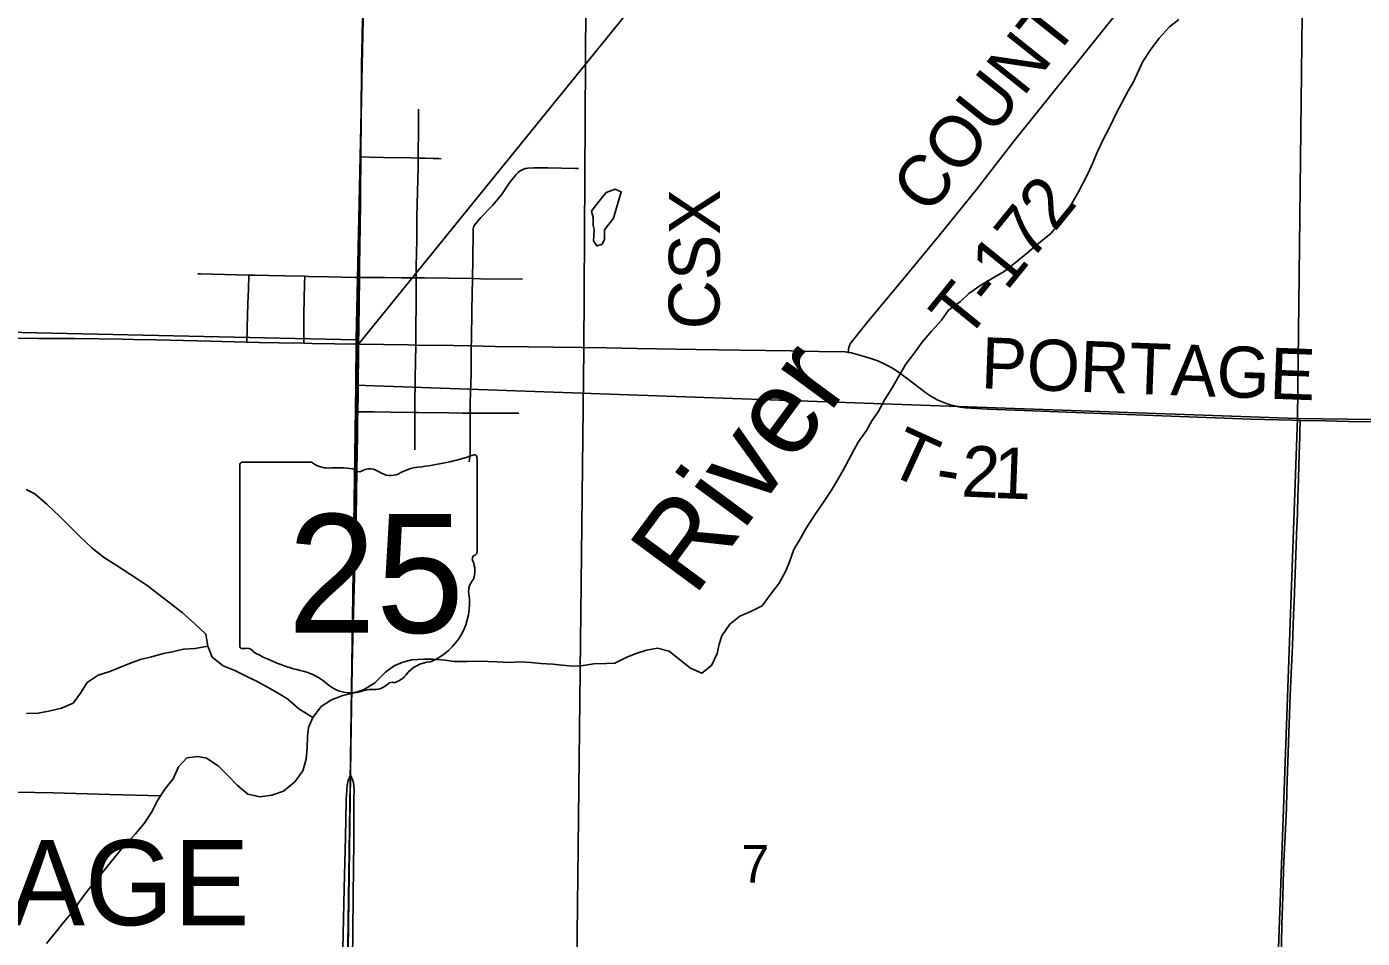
# Model space of a CAD drawing. Extents: x -107 to 120, y -81 to 213.
# Drawn here: x -76.39 to -68.55, y -30.12 to -24.78 of the extents above; entities that cross this region are included whole.
import ezdxf

# ---------------------------------------------------------------- set-up
doc = ezdxf.new("R2010")
doc.units = 0
for name, color, linetype in [('Default', 7, 'Continuous'), ('GM_X_City_Street', 7, 'Continuous'), ('GM_X_Corporation_Text', 7, 'Continuous'), ('GM_X_Major_River', 7, 'Continuous'), ('GM_X_Minor_Lake', 7, 'Continuous'), ('GM_X_Minor_River', 7, 'Continuous'), ('GM_X_Minor_River_Text', 7, 'Continuous'), ('GM_X_Rail_Line', 7, 'Continuous'), ('GM_X_Rail_Line_Text', 7, 'Continuous'), ('GM_X_Section', 7, 'Continuous'), ('GM_X_Section_Text', 7, 'Continuous'), ('GM_X_State_Location', 7, 'Continuous'), ('GM_X_State_Route', 7, 'Continuous'), ('GM_X_State_Shield', 7, 'Continuous'), ('GM_X_Township', 7, 'Continuous'), ('GM_X_Township_Road', 7, 'Continuous'), ('GM_X_Township_Road_Text', 7, 'Continuous')]:
    doc.layers.add(name, color=color, linetype=linetype)

msp = doc.modelspace()

# ---------------------------------------------------------------- linework, layer by layer
at = {"layer": 'Default'}
msp.add_line((-74.4427, -26.637), (119.9981, 213.2739), dxfattribs=at)
at = {"layer": 'GM_X_City_Street'}
for points in [[(-74.1072, -26.6428), (-74.1072, -26.6296), (-74.1074, -26.5878), (-74.1066, -26.5245), (-74.1061, -26.4914), (-74.1056, -26.4507), (-74.1052, -26.4185), (-74.1051, -26.3742), (-74.1051, -26.3129), (-74.1049, -26.2909), (-74.1045, -26.2483), (-74.1042, -26.2136), (-74.1039, -26.1701), (-74.1034, -26.1146), (-74.1009, -26.0166), (-74.1007, -25.9843), (-74.1006, -25.9353), (-74.1003, -25.9203), (-74.0999, -25.8891), (-74.0936, -25.5993), (-74.0936, -25.5505), (-74.0935, -25.5459), (-74.093, -25.518), (-74.0932, -25.502), (-74.0919, -25.4041), (-74.0914, -25.3665), (-74.0907, -25.3064), (-74.09, -25.2594)], [(-74.4297, -25.5388), (-74.3782, -25.5402), (-74.2972, -25.5425), (-74.1348, -25.5444), (-74.0935, -25.5459), (-74.0538, -25.5473), (-74.0054, -25.5482), (-73.9733, -25.5494), (-73.9575, -25.5503)], [(-73.7813, -26.6482), (-73.7808, -26.6156), (-73.778, -26.4355), (-73.7745, -26.2534), (-73.7724, -26.1409), (-73.7708, -25.9772), (-73.7697, -25.9609), (-73.7654, -25.9452), (-73.7567, -25.9315), (-73.7459, -25.9191), (-73.7244, -25.8951), (-73.6558, -25.8248), (-73.6349, -25.7997), (-73.6047, -25.761), (-73.5582, -25.6936), (-73.5286, -25.6544), (-73.5181, -25.6419), (-73.5066, -25.6302), (-73.4936, -25.6203), (-73.4792, -25.6127), (-73.4637, -25.6077), (-73.4476, -25.6049), (-73.4149, -25.603), (-73.333, -25.6029), (-73.1693, -25.6071), (-73.153, -25.6073)], [(-75.386, -26.2245), (-75.37, -26.2245), (-75.0867, -26.2331), (-75.0515, -26.2336), (-74.9716, -26.2349), (-74.8754, -26.2364), (-74.7582, -26.2396), (-74.737, -26.2399), (-74.6164, -26.2425), (-74.4626, -26.2458), (-74.4378, -26.2464)], [(-75.0981, -26.6259), (-75.0974, -26.602), (-75.0965, -26.5701), (-75.0956, -26.5371), (-75.0938, -26.4728), (-75.0917, -26.3981), (-75.0893, -26.3147), (-75.0867, -26.2331)], [(-74.7646, -26.6325), (-74.7643, -26.5961), (-74.7633, -26.4641), (-74.7592, -26.2827), (-74.7582, -26.2396)], [(-74.4378, -26.2464), (-74.2889, -26.247), (-74.188, -26.248), (-74.1045, -26.2483), (-74.0561, -26.2484), (-73.7745, -26.2534), (-73.7264, -26.2543), (-73.4813, -26.2565)], [(-74.1119, -27.2584), (-74.1124, -27.2262), (-74.1128, -27.194), (-74.1126, -27.1778), (-74.1127, -27.0799), (-74.1132, -27.0506), (-74.1134, -27.0383), (-74.1132, -26.9998), (-74.112, -26.9511), (-74.1111, -26.8862), (-74.111, -26.8537), (-74.1101, -26.8375), (-74.1082, -26.7398), (-74.1072, -26.6428)], [(-73.7937, -27.3273), (-73.7901, -27.3013), (-73.7887, -27.2789), (-73.7879, -27.261), (-73.7874, -27.224), (-73.7879, -27.1423), (-73.7877, -27.0771), (-73.7882, -27.0418), (-73.7879, -27.0252), (-73.7869, -26.9797), (-73.7836, -26.865), (-73.7829, -26.8156), (-73.7813, -26.6482)], [(-74.4474, -27.0348), (-74.4069, -27.0345), (-74.3528, -27.0341), (-74.2547, -27.0359), (-74.1134, -27.0383), (-74.0932, -27.0386), (-73.9111, -27.0415), (-73.8305, -27.0417), (-73.7882, -27.0418), (-73.7391, -27.0419), (-73.6821, -27.042), (-73.5839, -27.0428), (-73.5513, -27.043), (-73.5029, -27.0427)]]:
    msp.add_lwpolyline(points, dxfattribs=at)
at = {"layer": 'GM_X_Major_River'}
for points in [[(-69.6305, -24.7339), (-69.6847, -24.7759), (-69.745, -24.8419), (-69.7953, -24.9119), (-69.8416, -24.98), (-69.8739, -25.0521), (-69.8981, -25.1022), (-69.9262, -25.1522), (-69.9625, -25.2183), (-69.9968, -25.2844), (-70.0331, -25.3585), (-70.0714, -25.4326), (-70.1056, -25.5027), (-70.1339, -25.5748), (-70.1641, -25.6389), (-70.1904, -25.691), (-70.2186, -25.7431), (-70.2488, -25.7991), (-70.2891, -25.8632), (-70.3213, -25.9173), (-70.3796, -25.9873), (-70.4539, -26.0472), (-70.5162, -26.0992), (-70.5905, -26.1612), (-70.6547, -26.2111), (-70.719, -26.249), (-70.7912, -26.2909), (-70.8615, -26.3409), (-70.9117, -26.3869), (-70.982, -26.4388), (-71.0223, -26.4969), (-71.0805, -26.5609), (-71.1348, -26.6269), (-71.1871, -26.6969), (-71.2314, -26.755), (-71.2717, -26.825), (-71.312, -26.8931), (-71.3543, -26.9632), (-71.3946, -27.0353), (-71.4308, -27.0873), (-71.463, -27.1434), (-71.5113, -27.2134), (-71.5496, -27.2855), (-71.5879, -27.3556), (-71.6241, -27.4217), (-71.6684, -27.4937), (-71.7188, -27.5698), (-71.7691, -27.6458), (-71.8154, -27.7179), (-71.8476, -27.774), (-71.8879, -27.842), (-71.9162, -27.9202), (-71.9384, -27.9722), (-71.9747, -28.0403), (-72.027, -28.1084), (-72.0753, -28.1724), (-72.1415, -28.2063), (-72.2057, -28.2342)], [(-72.2057, -28.2342), (-72.2639, -28.2801), (-72.3102, -28.3482), (-72.3264, -28.3983), (-72.3386, -28.4524), (-72.3709, -28.5225), (-72.4291, -28.5684), (-72.4951, -28.5381), (-72.5591, -28.4878), (-72.621, -28.4395), (-72.6891, -28.4213), (-72.7532, -28.4331), (-72.8194, -28.455), (-72.8716, -28.4769), (-72.9398, -28.5088), (-72.9899, -28.5106), (-73.062, -28.5124), (-73.1362, -28.5242), (-73.1862, -28.5261), (-73.2503, -28.5219), (-73.3024, -28.5157), (-73.3725, -28.5115), (-73.4326, -28.5053), (-73.4947, -28.5011), (-73.5588, -28.5049), (-73.6289, -28.5007), (-73.683, -28.4985), (-73.7531, -28.4983), (-73.8052, -28.5002), (-73.8813, -28.5), (-73.9354, -28.4918), (-74.0075, -28.4855), (-74.0596, -28.4854), (-74.1297, -28.4892), (-74.1838, -28.5031), (-74.234, -28.525), (-74.2842, -28.5629), (-74.3465, -28.6249), (-74.4128, -28.6648), (-74.4769, -28.6847), (-74.5351, -28.6986), (-74.6013, -28.7244), (-74.6615, -28.7644), (-74.7118, -28.8284), (-74.736, -28.8865), (-74.7422, -28.9366), (-74.7444, -29.0068), (-74.7506, -29.0729), (-74.7689, -29.1411), (-74.8171, -29.2051), (-74.8834, -29.261), (-74.9516, -29.2829), (-75.0198, -29.2927), (-75.0918, -29.2785), (-75.1558, -29.2241), (-75.2037, -29.1739), (-75.2656, -29.1115), (-75.3356, -29.0672), (-75.3856, -29.057), (-75.4498, -29.0648), (-75.5, -29.1168), (-75.5303, -29.1869), (-75.5786, -29.249), (-75.6249, -29.319), (-75.6551, -29.3811), (-75.7014, -29.4491), (-75.7517, -29.5111), (-75.82, -29.5831), (-75.8743, -29.6491), (-75.9286, -29.7172), (-75.9809, -29.7812), (-76.0352, -29.8472), (-76.0835, -29.9132), (-76.1197, -29.9653), (-76.1761, -30.0333), (-76.2203, -30.0893), (-76.2746, -30.1533)]]:
    msp.add_lwpolyline(points, dxfattribs=at)
at = {"layer": 'GM_X_Minor_Lake'}
msp.add_line((-73.066, -25.9413), (-73.06, -25.9654), dxfattribs=at)
msp.add_lwpolyline([(-73.06, -25.9654), (-73.0621, -26.0015), (-73.0642, -26.0316), (-73.0443, -26.0617), (-73.0162, -26.0538), (-73.0001, -26.0237), (-72.9999, -25.9676), (-72.9476, -25.8995), (-72.9011, -25.7432), (-72.9371, -25.7291), (-72.9892, -25.747), (-73.0154, -25.779), (-73.0536, -25.829), (-73.0757, -25.857), (-73.0658, -25.8952), (-73.066, -25.9413)], dxfattribs=at)
at = {"layer": 'GM_X_Minor_River'}
for points in [[(-74.7118, -28.8284), (-74.7937, -28.778), (-74.8577, -28.7197), (-74.9137, -28.6854), (-74.9776, -28.6491), (-75.0336, -28.6189), (-75.1017, -28.5846), (-75.1677, -28.5523), (-75.2377, -28.524), (-75.3016, -28.4737), (-75.3275, -28.4094), (-75.3393, -28.3392), (-75.4072, -28.2748), (-75.4751, -28.2145), (-75.5551, -28.1521), (-75.623, -28.0997), (-75.677, -28.0574), (-75.7409, -28.0151), (-75.8649, -27.9346), (-75.9329, -27.8922), (-76.0048, -27.8339), (-76.0807, -27.7635), (-76.1945, -27.6488), (-76.2724, -27.5764), (-76.3424, -27.516), (-76.3932, -27.4909)], [(-87.8579, -27.654), (-87.8652, -28.0711), (-87.865, -28.6186), (-87.8721, -28.9735), (-87.6537, -28.9782), (-86.7323, -28.995), (-86.0953, -29.0149), (-85.6165, -29.0284), (-85.272, -29.0455), (-84.7492, -29.0571), (-83.7757, -29.1001), (-82.8864, -29.1348), (-81.8969, -29.1759), (-81.2178, -29.198), (-80.2463, -29.221), (-79.6213, -29.2289), (-78.4253, -29.2485), (-77.3656, -29.2537), (-76.8808, -29.2591), (-76.2337, -29.2691), (-75.9012, -29.2801), (-75.6037, -29.287)], [(-75.3275, -28.4094), (-75.4016, -28.4233), (-75.4698, -28.4271), (-75.5359, -28.4429), (-75.588, -28.4528), (-75.6582, -28.4726), (-75.7224, -28.4885), (-75.7765, -28.5064), (-75.8488, -28.5362), (-75.9029, -28.5581), (-75.9711, -28.58), (-76.0353, -28.6219), (-76.0736, -28.686), (-76.1179, -28.744), (-76.1861, -28.7739), (-76.2522, -28.7897), (-76.3224, -28.8035), (-76.3905, -28.8054)]]:
    msp.add_lwpolyline(points, dxfattribs=at)
at = {"layer": 'GM_X_Rail_Line'}
for points in [[(-73.2734, -42.3003), (-73.2649, -39.1049), (-73.2216, -37.066), (-73.1836, -32.1627), (-73.1217, -26.6694), (-73.1077, -24.2984), (-73.0594, -17.2912), (-73.0254, -15.4202), (-73.0009, -14.7079), (-72.9769, -14.4026), (-72.9056, -13.7921), (-72.6989, -11.6944), (-72.6592, -11.2717), (-72.6185, -10.8402), (-72.6072, -10.5527), (-72.6015, -10.2681), (-72.5873, -9.1338), (-72.5717, -7.0133)], [(-74.7234, -53.134), (-74.6362, -47.8623), (-74.5798, -37.2388), (-74.4951, -29.4853), (-74.4481, -26.6247), (-74.401, -23.7172), (-74.3109, -18.2221), (-74.335, -14.312), (-74.2191, -9.0155)]]:
    msp.add_lwpolyline(points, dxfattribs=at)
at = {"layer": 'GM_X_Section'}
for points in [[(-79.6709, -20.7861), (-74.3332, -20.9721), (-74.4572, -26.6128), (-79.8137, -26.4946)], [(-74.3332, -20.9721), (-69.0434, -21.1516), (-68.8654, -21.1579), (-68.9331, -27.0735), (-74.4587, -26.8789), (-74.4572, -26.6128)], [(-68.8654, -21.1579), (-63.5863, -21.3171), (-63.5383, -21.3196), (-63.6604, -27.1446), (-68.9331, -27.0735)], [(-79.8137, -26.4946), (-74.4572, -26.6128), (-74.4587, -26.8789), (-74.5311, -31.9421), (-79.8737, -31.8319)], [(-74.4587, -26.8789), (-68.9331, -27.0735), (-69.1226, -32.3632), (-74.5279, -32.1542), (-74.5311, -31.9421)], [(-68.9331, -27.0735), (-63.6604, -27.1446), (-63.7963, -32.4291), (-69.1226, -32.3632)]]:
    msp.add_lwpolyline(points, close=True, dxfattribs=at)
at = {"layer": 'GM_X_State_Route'}
for p, q in [((-74.515, -29.3224), (-74.5145, -29.3014)), ((-74.5196, -29.5272), (-74.515, -29.3224))]:
    msp.add_line(p, q, dxfattribs=at)
for points in [[(-74.4313, -25.7287), (-74.4303, -25.5642), (-74.4297, -25.5388), (-74.4285, -25.4823), (-74.4272, -25.3597), (-74.4264, -25.2802), (-74.4258, -25.2195), (-74.4244, -25.0885), (-74.4234, -25.0056), (-74.4223, -24.9089), (-74.4212, -24.8458), (-74.4201, -24.8081), (-74.4098, -24.5459)], [(-74.437, -26.1834), (-74.4341, -25.9417), (-74.4322, -25.8106), (-74.4314, -25.7446), (-74.4313, -25.7287)], [(-74.4427, -26.637), (-74.4413, -26.5488), (-74.4396, -26.4014), (-74.4378, -26.2464), (-74.437, -26.1834)], [(-74.4536, -27.4369), (-74.4526, -27.3749), (-74.4496, -27.1799), (-74.448, -27.0774), (-74.4474, -27.0348), (-74.4458, -26.9287), (-74.4427, -26.637)], [(-74.4619, -27.8587), (-74.4584, -27.733), (-74.4552, -27.5363), (-74.4539, -27.4576), (-74.4536, -27.4369)], [(-74.4893, -29.1668), (-74.4838, -28.689), (-74.4803, -28.5185), (-74.4717, -28.2095), (-74.4619, -27.8587)], [(-74.5145, -29.3014), (-74.5142, -29.2827), (-74.5122, -29.252), (-74.5089, -29.2241), (-74.5032, -29.1979), (-74.4893, -29.1668)], [(-74.4698, -29.3014), (-74.4688, -29.2536), (-74.4696, -29.2323), (-74.4729, -29.2093), (-74.4778, -29.1946), (-74.4893, -29.1668)], [(-74.4705, -29.552), (-74.4701, -29.4294), (-74.4698, -29.3014)], [(-74.5364, -30.277), (-74.5264, -29.8318), (-74.5196, -29.5272)], [(-74.4841, -30.7023), (-74.4808, -30.3991), (-74.4769, -30.0872), (-74.4741, -29.8739), (-74.4705, -29.552)]]:
    msp.add_lwpolyline(points, dxfattribs=at)
at = {"layer": 'GM_X_State_Shield'}
for p, q in [((-75.1399, -27.3489), (-75.1399, -28.4055)), ((-74.7185, -27.3307), (-75.1262, -27.3307)), ((-73.7477, -27.8573), (-73.7477, -27.3045)), ((-73.7479, -27.8571), (-73.7477, -27.8573))]:
    msp.add_line(p, q, dxfattribs=at)
for centre, radius, start, end in [((-75.1239, -27.3466), 0.0161, 98.1301, 188.1301), ((-74.6214, -27.208), 0.1564, 231.61951, 271.11188), ((-74.2436, -25.8902), 1.4764, 275.84447, 288.90645), ((-73.7632, -27.3022), 0.0155, 351.86209, 97.738), ((-74.5695, -27.9239), 0.5616, 80.48669, 94.98827), ((-74.442, -27.3412), 0.0451, 219.79206, 297.10237), ((-74.3758, -27.4633), 0.0938, 54.46668, 119.14113), ((-74.2547, -27.2958), 0.1129, 233.85621, 294.82819), ((-74.0553, -27.6534), 0.297, 97.34618, 120.76885), ((-73.7513, -27.8978), 0.024, 107.94398, 210.33697), ((-73.7643, -27.8594), 0.0166, 289.60381, 7.73413), ((-73.9039, -27.9677), 0.144, 340.03296, 23.64957), ((-73.6922, -28.0886), 0.1048, 136.8065, 186.92959), ((-74.1609, -28.1589), 0.3693, 292.30889, 8.98584), ((-75.1238, -28.4078), 0.0163, 171.95839, 258.30661), ((-75.1213, -28.2997), 0.1242, 267.33899, 280.60386), ((-75.0959, -28.4665), 0.0448, 29.74838, 93.27175), ((-74.5307, -27.5171), 1.0661, 240.41292, 257.1985), ((-74.0052, -28.7022), 0.2022, 94.40312, 142.57675), ((-74.8485, -28.8802), 0.3336, 47.18416, 75.83597), ((-74.2615, -28.5079), 0.1193, 282.87319, 323.27711), ((-74.4877, -28.4717), 0.2117, 230.70037, 286.29184), ((-74.3654, -28.8371), 0.1739, 85.69512, 111.20995), ((-74.35, -28.5509), 0.1128, 268.77702, 315.54927), ((-74.2479, -28.6532), 0.0318, 65.75173, 132.64842)]:
    msp.add_arc(centre, radius, start, end, dxfattribs=at)
at = {"layer": 'GM_X_Township'}
for points in [[(-74.411, -24.543), (-74.4213, -24.8052), (-74.4224, -24.8429), (-74.4235, -24.906), (-74.4246, -25.0027), (-74.4256, -25.0856), (-74.427, -25.2166), (-74.4276, -25.2772), (-74.4284, -25.3567), (-74.4297, -25.4794), (-74.4309, -25.5359), (-74.4315, -25.5613), (-74.4326, -25.7416), (-74.4334, -25.8077), (-74.4353, -25.9388), (-74.439, -26.2435), (-74.4408, -26.3985), (-74.4425, -26.5459), (-74.4439, -26.6341), (-74.447, -26.9258), (-74.4486, -27.0319), (-74.4492, -27.0744), (-74.4508, -27.1769), (-74.4538, -27.372), (-74.4551, -27.4547), (-74.4564, -27.5334), (-74.4596, -27.7301), (-74.4729, -28.2066), (-74.4815, -28.5156), (-74.485, -28.6861), (-74.4905, -29.1638), (-74.5268, -31.9421)], [(-74.5268, -31.9421), (-74.4905, -29.1638), (-74.485, -28.6861), (-74.4815, -28.5156), (-74.4729, -28.2066), (-74.4596, -27.7301), (-74.4564, -27.5334), (-74.4551, -27.4547), (-74.4538, -27.372), (-74.4508, -27.1769), (-74.4492, -27.0744), (-74.4486, -27.0319), (-74.447, -26.9258), (-74.4439, -26.6341), (-74.4425, -26.5459), (-74.4408, -26.3985), (-74.439, -26.2435), (-74.4353, -25.9388), (-74.4334, -25.8077), (-74.4326, -25.7416), (-74.4315, -25.5613), (-74.4309, -25.5359), (-74.4297, -25.4794), (-74.4284, -25.3567), (-74.4276, -25.2772), (-74.427, -25.2166), (-74.4256, -25.0856), (-74.4246, -25.0027), (-74.4235, -24.906), (-74.4224, -24.8429), (-74.4213, -24.8052), (-74.411, -24.543)]]:
    msp.add_lwpolyline(points, dxfattribs=at)
at = {"layer": 'GM_X_Township_Road'}
msp.add_line((-68.9178, -27.0849), (-68.7709, -27.0883), dxfattribs=at)
for points in [[(-71.5684, -26.6858), (-71.5674, -26.6679), (-71.5656, -26.6566), (-71.5623, -26.6448), (-71.5552, -26.6304), (-71.5454, -26.6174), (-71.4518, -26.5033), (-71.2738, -26.2887), (-71.0336, -25.9979), (-70.8178, -25.7296), (-70.7369, -25.6263), (-70.5954, -25.4456), (-70.3489, -25.1388), (-70.2256, -24.9854), (-69.9802, -24.6777)], [(-76.8191, -26.5969), (-76.6656, -26.5998), (-76.3209, -26.6042), (-76.1075, -26.6053), (-75.8286, -26.6086), (-75.7632, -26.6104), (-75.6326, -26.6133), (-75.3868, -26.619), (-75.1735, -26.6239), (-75.0981, -26.6259)], [(-75.0981, -26.6259), (-75.026, -26.6278), (-74.911, -26.6299), (-74.7646, -26.6325)], [(-74.7646, -26.6325), (-74.7178, -26.6333), (-74.5828, -26.6356), (-74.4427, -26.637)], [(-74.4427, -26.637), (-74.1495, -26.6421), (-74.1072, -26.6428)], [(-74.1072, -26.6428), (-73.8876, -26.6464), (-73.7813, -26.6482)], [(-73.7813, -26.6482), (-73.6419, -26.6505), (-73.4454, -26.6534), (-73.298, -26.6554), (-73.1343, -26.6576), (-72.9871, -26.6595), (-72.807, -26.6641), (-72.6923, -26.6657), (-72.4631, -26.6684), (-72.2011, -26.672), (-71.9063, -26.6759), (-71.7427, -26.6801), (-71.6433, -26.6818)], [(-71.6433, -26.6818), (-71.6119, -26.6814), (-71.5884, -26.6832), (-71.5734, -26.6851), (-71.5684, -26.6858)], [(-71.5684, -26.6858), (-71.5504, -26.6889), (-71.5305, -26.6936), (-71.4896, -26.7053), (-71.442, -26.7192), (-71.3955, -26.7364), (-71.3503, -26.7568), (-71.3068, -26.7806), (-71.2609, -26.8124), (-71.1905, -26.8654), (-71.1149, -26.9227), (-71.0854, -26.9431), (-71.0632, -26.9555), (-71.0472, -26.9635), (-71.0185, -26.9756), (-70.9898, -26.9869), (-70.9608, -26.9952), (-70.9294, -27.0036), (-70.9106, -27.007), (-70.884, -27.0106), (-70.8489, -27.0138), (-70.7507, -27.0193), (-70.5374, -27.0273), (-69.8814, -27.0532), (-69.2088, -27.0774), (-68.9627, -27.0839), (-68.9178, -27.0849)], [(-69.0153, -29.7263), (-69.0138, -29.6704), (-69.0067, -29.523), (-68.9987, -29.3593), (-68.9954, -29.2642), (-68.9935, -29.1953), (-68.9882, -29.0346), (-68.9836, -28.9166), (-68.9821, -28.8674), (-68.9782, -28.7526), (-68.9721, -28.6116), (-68.9636, -28.4084), (-68.9569, -28.2248), (-68.9538, -28.1494), (-68.9478, -27.9854), (-68.9439, -27.8739), (-68.9374, -27.7034), (-68.9362, -27.6773), (-68.9344, -27.6248), (-68.9312, -27.5298), (-68.9298, -27.4904), (-68.9227, -27.2838), (-68.9199, -27.1788), (-68.9191, -27.1363), (-68.9182, -27.1013), (-68.9178, -27.0849)], [(-68.7709, -27.0883), (-68.6345, -27.0914), (-68.4705, -27.0934), (-68.1916, -27.0967), (-68.0275, -27.0972), (-67.8273, -27.1011), (-67.7187, -27.103), (-67.5023, -27.1059), (-67.2564, -27.1097), (-67.0431, -27.1119), (-66.8461, -27.1153), (-66.7615, -27.1159)], [(-69.0882, -32.3551), (-69.0863, -32.2659), (-69.0703, -31.6759), (-69.0563, -31.1374), (-69.0474, -30.8493), (-69.0405, -30.6253), (-69.0346, -30.4447), (-69.0297, -30.2642), (-69.0252, -30.0409), (-69.0224, -29.9358), (-69.02, -29.8801), (-69.0153, -29.7263)]]:
    msp.add_lwpolyline(points, dxfattribs=at)

# ---------------------------------------------------------------- texts
at = {"layer": 'GM_X_Corporation_Text'}
msp.add_text('PORTAGE', height=0.5, rotation=0.00001, dxfattribs=at).set_placement((-78.3511, -30.0466))
at = {"layer": 'GM_X_Minor_River_Text'}
msp.add_text('River', height=0.50027, rotation=53.62845, dxfattribs=at).set_placement((-72.4737, -28.1262))
at = {"layer": 'GM_X_Rail_Line_Text'}
msp.add_text('CSX', height=0.299, rotation=89.73488, dxfattribs=at).set_placement((-72.3253, -26.5514))
at = {"layer": 'GM_X_Section_Text'}
msp.add_text('7', height=0.221, rotation=0.00001, dxfattribs=at).set_placement((-72.1967, -29.7962))
at = {"layer": 'GM_X_State_Location'}
for s in ['s', 'r']:
    msp.add_text(s, height=0.001, dxfattribs=at).set_placement((-74.4595, -27.9475))
msp.add_text('25', height=0.001, rotation=0.00001, dxfattribs=at).set_placement((-74.7113, -28.0202))
at = {"layer": 'GM_X_State_Shield'}
msp.add_text('25', height=0.6961, dxfattribs=at).set_placement((-74.8584, -28.331))
at = {"layer": 'GM_X_Township_Road_Text'}
for s, rotation, p in [('COUNTY', 51.41746, (-71.0991, -25.8891)), ('T-172', 50.94582, (-70.8791, -26.6255)), ('PORTAGE', 357.92854, (-70.7941, -26.8962)), ('T', 335.45744, (-71.3556, -27.3887)), ('2', 357.2918, (-70.9095, -27.5308)), ('1', 357.76643, (-70.7222, -27.5397)), ('-', 350.76945, (-71.0681, -27.5072))]:
    msp.add_text(s, height=0.3, rotation=rotation, dxfattribs=at).set_placement(p)

doc.saveas('drawing.dxf')
